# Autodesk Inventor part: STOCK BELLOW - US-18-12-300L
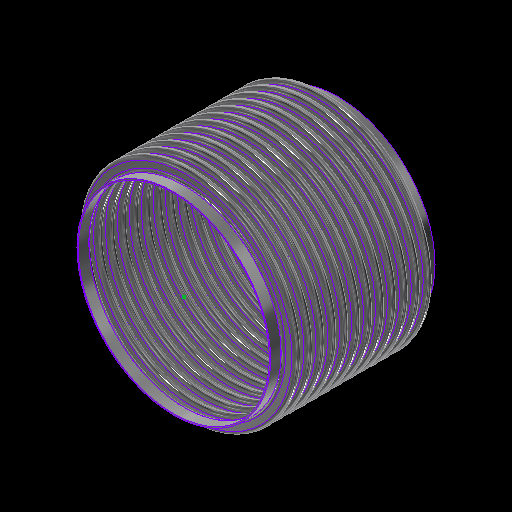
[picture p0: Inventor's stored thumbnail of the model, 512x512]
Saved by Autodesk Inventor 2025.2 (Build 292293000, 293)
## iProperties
Category: 16 GA (0.060 THICK)
RuleStatus: InUse
Created: 2024-01
Part Number: STOCK BELLOW - US-18-12-300L
Project: =STOCK BELLOWS: <Stock Number><SFILL>
Material: ASTM A240-304
Description: =STOCK BELLOWS: <Stock Number>, <SID_> I.D., <SOD_> O.D., <SPLY_> PLY, <Category>, <SNET_CONS> CONS.<PITCH_><STANGENT_> TANGENT<SFILL>
Document SubType Name: Sheet Metal
Designer: GS
Stock Number: U.S-18-12-300L
Surface Area: 28909 cm^2
Volume: 4365.44 cm^3
Sheet Metal Rule: Default
Appearance: STAINLESS STEEL
Mass: 35173.6 g
Density: 8.05729 g/cm^3
THK: 0.036
ID: 3.500
OD: 4.250
CONS_: 2
PITCH: 0.500
TANGENT: 0.500
BELLOWS_UPSET: 0.000
d79: 1.000
d82: 1.000
d83: 26.000
d84: 24.000
d174: 8
d214: 8
STHK_: 0.060
SID_: 18.000
SOD_: 20.500
SPITCH_: 1.125
STANGENT__: 1.000
SBELLOWS_UPSET_: 0.000
SDIFF_TAN: 1.000
d252: 2
d275: 2
d287: 0.050
d289: 0.500
d290: 0.000
SOD_NECK: 18 1/4
PLY: 1
PSET: 4.178
PBAR: 1.035
COUNTER: 1.500
NET_TUBE: 3.071
CONS: 2
S_CONS: 0
NET_CONS: 2
ID_M: 88.90 mm
OD_M: 107.95 mm
THK_M: 0.91 mm
ID_U: 3.500 in
OD_U: 4.250 in
THK_U: 0.036 in
TANGENT2: 0.500
TAN_TO_TAN: 1.000 in
d80: 2.571
d81: 10
SID: 2.375
SCONS_: 12
SPITCH: 0.250
STANGENT_: 1.000
SBELLOWS_UPSET: 0.000
SNET_CONS: 12
SS_CONS: 0
SCONS: 8
d190: 8
d191: 1
d192: 1
d193: 8
d194: 0
SIZE: 18.00
PRESSURE: 300
d230: 8
STANGENT: 4.000
SPLY_: 2
d233: 8
d234: 0
d263: 2
d265: 1
d268: 2
d269: 0
d286: 2
d288: 1
d291: 2
d292: 0
SREROLL: 0.750
BLETP: 1.000 ul
PRES_Copy: 85
MATTABLE: 20 GA (0.036 THICK)
PART_NUMBER: U.S-18-12-300L
PITCH_: =, <SPITCH_> PITCH,
CFILL: .
SFILL: .
MESH: ,
COMP: 2.29
EXT: 1.15
LAT: 0.53
ANG: 573
ASR: 7081
LSR: 21595
ANSR: 5724
PRES: 300
COMPM: 22.9
EXTM: 11.45
LATM: 5.30
ASRM: 1240.096
PRESM: 20.684
LSRM: 3781.932
ANSRM: 1002.444
TEMPMIN: 20
TEMPMAX: 800
TEMPMINM: -7
TEMPMAXM: 427
WEIGHTM: 35.174
WEIGHT: 77.544
Author: GS
Keywords: 20 GA (0.036 THICK)
Comments: =STOCK BELLOW - <STOCK NUMBER>
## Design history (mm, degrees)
sketch "Sketch2"
  geometry: L1 (0, -177.245)-(0, 562.856) reference; L2 (45.364, 0)-(44.45, 0); L3 (48.082, -2.718)-(50.343, -2.718); L4 (48.082, -3.632)-(50.343, -3.632); L5 (50.343, -9.982)-(48.082, -9.982); L6 (50.343, -9.068)-(48.082, -9.068); L7 (45.364, -12.7)-(44.45, -12.7); L8 (48.082, 0)-(48.082, -12.7); L9 (50.343, -6.35)-(53.975, -6.35); L10 (44.45, 0)-(44.45, -12.7); L11 (20.376, 102.841)-(20.376, 101.926); L12 (58.262, 457.127)-(58.262, 349.177); L13 (58.262, 444.427)-(58.262, 336.477); L14 (93.133, -58.817)-(93.133, -71.517); L15 (118.746, -66.401)-(118.746, -66.401); L16 (50.343, -9.068)-(50.343, -9.982); L17 (48.082, -9.068)-(48.082, -9.982); L18 (48.082, -9.525)-(50.343, -9.525); L19 (53.975, 0)-(53.975, -12.7); L20 (-50.343, -9.068)-(-50.343, -9.982); L21 (-50.343, -2.718)-(-48.082, -2.718); L22 (-50.343, -3.632)-(-48.082, -3.632); L23 (-48.082, -9.068)-(-50.343, -9.068); L24 (-50.343, -9.525)-(-48.082, -9.525); L25 (-48.082, -9.982)-(-50.343, -9.982); L26 (-48.082, -9.068)-(-48.082, -9.982); L27 (-44.45, 0.653)-(-44.45, -12.047); L28 (-48.082, -6.35)-(-44.45, -6.35); L29 (-50.343, 0.653)-(-50.343, -12.7); L30 (-53.061, 0)-(-53.975, 0); L31 (-53.975, 0)-(-53.975, -12.7); L32 (-53.061, -12.7)-(-53.975, -12.7); A1 r 2.718 centre (48.082, 0) between (45.364, 0) and (48.082, -2.718); A2 r 3.632 centre (48.082, 0) between (44.45, 0) and (48.082, -3.632); A3 r 3.632 centre (50.343, -6.35) between (50.343, -9.982) and (50.343, -2.718); A4 r 2.718 centre (50.343, -6.35) between (50.343, -9.068) and (50.343, -3.632); A5 r 2.718 centre (48.082, -12.7) between (48.082, -9.982) and (45.364, -12.7); A6 r 3.632 centre (48.082, -12.7) between (48.082, -9.068) and (44.45, -12.7); A7 r 3.175 centre (50.343, -6.35) between (50.343, -9.525) and (53.518, -6.35); A8 r 3.175 centre (48.082, -12.7) between (48.082, -9.525) and (44.907, -12.7); A9 r 2.718 centre (-50.343, -12.7) between (-50.343, -9.982) and (-53.061, -12.7); A10 r 2.718 centre (-48.082, -6.35) between (-48.082, -9.068) and (-48.082, -3.632); A11 r 3.175 centre (-48.082, -6.35) between (-48.082, -9.525) and (-44.907, -6.35); A12 r 3.632 centre (-48.082, -6.35) between (-48.082, -9.982) and (-48.082, -2.718); A13 r 3.175 centre (-50.343, -12.7) between (-50.343, -9.525) and (-53.518, -12.7); A14 r 3.632 centre (-50.343, -12.7) between (-50.343, -9.068) and (-53.975, -12.7); A15 r 2.718 centre (-50.343, 0) between (-53.061, 0) and (-50.343, -2.718); A16 r 3.632 centre (-50.343, 0) between (-53.975, 0) and (-50.343, -3.632); 10 further points
  constraints: 62 end point, 38 point on circle, 20 tangent, 16 centre point, 12 parallel, 9 midpoint, 7 vertical, 6 coincident, 6 concentric, 6 point on line, 4 equal radius, 4 perpendicular, 3 horizontal, 1 collinear, 1 horizontal alignment, 10 other
  dimensions: "THK" = 0.9144 distance of L11.start L11.end; "ID" = 88.9 distance of L11.end point (20.376, 13.026); "OD" = 107.95 distance of L12.start L12.end; "PITCH" = 12.7 distance of L12.start L13.start; "TANGENT" = 12.7 distance of L14.start L14.end; "BELLOWS_UPSET" = 0 distance of L15.start L15.end; "d43" = 88.9 diameter of L10 L1 (= ID); "d44" = 107.95 diameter of L9.end L1 (= OD); "d45" = 0.9144 distance between parallel lines of L5 L6 (computed from THK, PLY); "d46" = 3.6322 radius of A3 (computed from PITCH, THK, PLY); "UPSET_PITCH" = 12.7 distance of L2.end L7.end (derived); "SIDEWALL_ANGLE" = 360 deg dimension on L3 L9 (derived); "CON_GAP" = 5.4356 distance of point (48.082, -9.068) point (48.082, -3.632) (derived); "TAN1" = 4.98728 dimension on A8 (derived); "TAN2" = 4.98728 dimension on A7 (derived); "LEG1" = 2.2606 distance of L18.start L18.end (derived); "d278" = 0.9144 distance between parallel lines of L25 L23 (derived); "d279" = 3.6322 radius of A12 (derived); "d280" = 12.7 distance of L30.end L31.end (derived); "d281" = 360 deg dimension on L21 L28 (derived); "d282" = 5.4356 distance of point (-50.343, -9.068) point (-50.343, -3.632) (derived); "d283" = 4.98728 dimension on A13 (derived); "d284" = 4.98728 dimension on A11 (derived); "d285" = 2.2606 distance of L24.start L24.end (derived); "d293" = 88.9 diameter of L27 L1 (derived); "d294" = 107.95 diameter of L31 L1 (derived)
  node "Sketch Rectangular Pattern1" dims "d31" = 25.4, "ID" = 88.9
  node "Sketch Rectangular Pattern2" dims "d39" = 25.4, "PITCH" = 12.7
revolve "CONS" stored, may be unused: angle "d48" = 90 deg
node "BELLOW MIDPLANE"
pattern_linear "Rectangular Pattern2" dims "d52" = 12.7 (= UPSET_PITCH)
sketch "Sketch5"
  geometry: C1 r 45.364 at (0, 0) reference; C2 r 44.45 at (0, 0) reference
extrude "TANGENT" new body sketch "Sketch5" distance "d53" = 12.7 (= TANGENT); taper "d54" = 0 deg
revolve "SAMETAN" stored, may be unused: angle "d65" = 90 deg
revolve "DIFFTAN" stored, may be unused: angle "d70" = 90 deg
sketch "Sketch9"
  geometry: L1 (53.319, 0)-(-53.319, 0) reference; L2 (0, -17.78)-(0, 17.78) reference; L3 (38.085, 0)-(-38.085, 0); L4 (38.085, -11.906)-(38.085, 11.906); L5 (25.385, -11.906)-(25.385, 11.906); L6 (13.15, 11.906)-(13.15, -11.906); L7 (-25.385, -11.906)-(-25.385, 11.906); L8 (-38.085, -11.906)-(-38.085, 11.906); L9 (37.291, -11.906)-(37.291, 11.906); L10 (38.085, -11.906)-(37.291, -11.906); L11 (38.085, 11.906)-(37.291, 11.906); L12 (13.546, 11.906)-(12.753, 11.906); L13 (12.753, 11.906)-(12.753, -11.906); L14 (12.753, -11.906)-(13.546, -11.906); L15 (13.546, -11.906)-(13.546, 11.906); L16 (-13.546, 11.906)-(-13.546, -11.906); L17 (-13.15, 11.906)-(-13.15, -11.906); L18 (-13.546, -11.906)-(-12.753, -11.906); L19 (-12.753, -11.906)-(-12.753, 11.906); L20 (-12.753, 11.906)-(-13.546, 11.906); L21 (-38.085, -11.906)-(-37.291, -11.906); L22 (-37.291, -11.906)-(-37.291, 11.906); L23 (-37.291, 11.906)-(-38.085, 11.906); L24 (-38.085, 11.906)-(-38.085, -11.906); L25 (38.085, -0.397)-(-38.085, -0.397); L26 (-38.085, -0.397)-(-38.085, 0.397); L27 (-38.085, 0.397)-(38.085, 0.397); L28 (38.085, 0.397)-(38.085, -0.397); L29 (-38.085, 11.906)-(38.085, 11.906); L30 (38.085, 11.906)-(38.085, 12.7); L31 (38.085, 12.7)-(-38.085, 12.7); L32 (-38.085, 12.7)-(-38.085, 11.906); L33 (38.085, -11.906)-(-38.085, -11.906); L34 (-38.085, -11.906)-(-38.085, -12.7); L35 (-38.085, -12.7)-(38.085, -12.7); L36 (38.085, -12.7)-(38.085, -11.906); 30 further points
  constraints: 68 end point, 13 midpoint, 13 parallel, 8 horizontal, 7 perpendicular, 6 equal length, 3 point on line, 2 vertical, 14 other
  dimensions: "d115" = 23.8125 distance of L4.start L4.end (derived); "d116" = 12.7 distance between parallel lines of L4 L5 (derived); "d117" = 12.23516 distance between parallel lines of L5 L6 (derived); "d125" = 38.53427 distance between parallel lines of L7 L6 (derived); "d127" = 12.7 distance between parallel lines of L8 L7 (derived); "d128" = 24.93516 distance between parallel lines of L6 L4 (derived); "d130" = 76.16943 distance between parallel lines of L8 L4 (derived); "RULER_THK" = 0.79375 distance between parallel lines of L4 L9; "d135" = 0.79375 distance of L13.end L14.end (derived); "d138" = 26.29911 distance of L13.end L16.end (derived); "d143" = 0.79375 distance of L22.end L8.end (derived); "d144" = 0.79375 distance between parallel lines of L27 L25 (derived)
extrude "RULER" join sketch "Sketch9" distance "d149" = 0.79375 (derived); taper "d150" = 0 deg
extrude "BARS" join sketch "Sketch9" distance "d151" = 0.79375 (derived); taper "d152" = 0 deg
pattern_linear "Rectangular Pattern4" dims "d155" = 26.29911 (derived)
sketch "Sketch13"
  geometry: L1 (93.149, -52.467)-(93.149, -77.867); L2 (231.648, 0)-(228.6, 0); L3 (231.648, -28.575)-(228.6, -28.575); L4 (251.682, -22.955)-(237.268, -22.955); L5 (251.682, -19.907)-(237.268, -19.907); L6 (251.682, -14.287)-(260.35, -14.287); L7 (237.268, -5.62)-(251.682, -5.62); L8 (237.268, 0)-(237.268, -28.575); L9 (228.6, 0)-(228.6, -28.575); L10 (58.254, 24.269)-(58.254, -496.431); L11 (58.254, -4.306)-(58.254, -525.006); L12 (58.254, -61.456)-(58.254, -582.156); L13 (58.254, -90.031)-(58.254, -610.731); L14 (58.254, -118.606)-(58.254, -639.306); L15 (58.254, -147.181)-(58.254, -667.881); L16 (58.254, -175.756)-(58.254, -696.456); L17 (58.254, -32.881)-(58.254, -553.581); L18 (20.376, 103.45)-(20.376, 101.926); L19 (237.268, -8.668)-(251.682, -8.668); L20 (0, -856.437)-(0, 263.431) reference; L21 (-52.07, 0)-(312.42, 0) reference; A1 r 5.62 centre (237.268, 0) between (231.648, 0) and (237.268, -5.62); A2 r 5.62 centre (237.268, -28.575) between (237.268, -22.955) and (231.648, -28.575); A3 r 8.668 centre (237.268, -28.575) between (237.268, -19.907) and (228.6, -28.575); A4 r 5.62 centre (251.682, -14.287) between (251.682, -19.907) and (251.682, -8.668); A5 r 8.668 centre (251.682, -14.287) between (251.682, -22.955) and (251.682, -5.62); A6 r 8.668 centre (237.268, 0) between (228.6, 0) and (237.268, -8.668); 6 further points; 1 other entity
  constraints: 38 end point, 15 point on circle, 9 tangent, 6 centre point, 6 parallel, 5 vertical alignment, 4 point on line, 4 vertical, 3 coincident, 3 concentric, 2 collinear, 2 equal radius, 1 horizontal, 1 perpendicular, 23 other
  dimensions: "SBELLOWS_UPSET_" = 0 distance of point (118.762, -66.401) point (118.762, -66.401); "STOTAL_THK_BELLOW__" = 3.048 distance between parallel lines of L4 L5 (derived); "d224" = 8.66775 radius of A5 (derived); "d225" = 28.575 distance of L2.end L3.end (derived); "SSIDEWALL_ANGLE_" = 360 deg dimension on L7 L6 (derived); "SSCON_GAP_" = 11.2395 distance of point (237.268, -19.907) point (237.268, -8.668) (derived); "d235" = 457.2 diameter of L9 L20 (derived); "d236" = 520.7 diameter of L6.end L20 (derived)
  node "Sketch Rectangular Pattern4" dims "d228" = 25.4
  node "Sketch Rectangular Pattern5" dims "d229" = 25.4
revolve "SBELLOW" stored, may be unused: angle "d197" = 90 deg
pattern_linear "Rectangular Pattern5" dims "d204" = 28.575 (derived)
revolve "STANGENT" stored, may be unused: angle "d240" = 90 deg
revolve "SSAMETAN" stored, may be unused: angle "d241" = 90 deg
revolve "SDIFFTAN" stored, may be unused: angle "d246" = 90 deg
revolve "INVCON" stored, may be unused: angle "d295" = 90 deg
pattern_linear "Rectangular Pattern6" dims "d298" = 12.7 (derived)
revolve "INVTANGENT" stored, may be unused: angle "d302" = 90 deg
revolve "INVSAMETAN" stored, may be unused: angle "d307" = 90 deg
revolve "INVDIFFTAN" stored, may be unused: angle "d312" = 90 deg
sketch "ID BELLOW MOUNT CALC"
  geometry: L1 (44.45, 0)-(38.1, 0); L2 (38.1, 0)-(38.1, 12.7); L3 (38.1, 12.7)-(44.45, 12.7); L4 (44.45, 12.7)-(44.45, 0); L5 (36.513, 12.7)-(35.598, 12.7); L6 (35.598, 12.7)-(35.598, 0); L7 (35.598, 0)-(36.513, 0); L8 (36.513, 0)-(36.513, 12.7); L9 (0, -2.54)-(0, 15.24) reference; L10 (-8.89, 0)-(53.34, 0) reference; 1 further point
  constraints: 16 end point, 5 parallel, 2 collinear, 2 horizontal, 2 perpendicular
  dimensions: "d314" = 12.7 distance of L5.end L6.end (derived); "d315" = 0.9144 distance of L5.start L5.end (derived); "IG" = 1.5875 distance between parallel lines of L2 L8; "PIPE_OD" = 88.9 diameter of L4 L9; "PIPE_WALL" = 6.35 distance of L2.end L3.end; "ID_MT_BELLOW" = 71.1962 diameter of L6 L9 (derived)
revolve "CFILL" stored, may be unused: angle "d320" = 90 deg
pattern_linear "Rectangular Pattern7" dims "d323" = 12.7 (derived)
revolve "SFILL" stored, may be unused: angle "d324" = 90 deg
pattern_linear "Rectangular Pattern8" dims "d327" = 28.575 (derived)
node "STOCK BELLOW MIDPLANE"
node "BELLOW"
sketch "Sketch6"
  geometry: L1 (-12.7, 45.364)-(0, 45.364); L2 (0, 45.364)-(0, 44.45); L3 (0, 44.45)-(-12.7, 44.45); L4 (-12.7, 44.45)-(-12.7, 45.364); L5 (10.16, 0)-(-60.96, 0) reference; L6 (-38.1, -89.422)-(-38.1, 153.44) reference; 1 further point
  constraints: 8 end point, 2 parallel, 1 horizontal, 1 perpendicular
  dimensions: "d61" = 12.7 distance of L2.end L3.end (derived); "d62" = 0.9144 distance of L1.end L2.end (derived); "d63" = 88.9 diameter of L3 L5 (derived); "d64" = 25.4 distance between parallel lines of L4 L6 (derived)
sketch "Sketch12"
  geometry: 1 further point
sketch "Sketch14"
  geometry: L1 (-25.4, 231.648)-(0, 231.648); L2 (0, 231.648)-(0, 228.6); L3 (0, 228.6)-(-25.4, 228.6); L4 (-25.4, 228.6)-(-25.4, 231.648); L5 (5.08, 0)-(-30.48, 0) reference; L6 (0, -46.33)-(0, 277.978) reference; 1 further point
  constraints: 8 end point, 2 parallel, 1 collinear, 1 horizontal, 1 perpendicular
  dimensions: "d237" = 3.048 distance of L3.end L1.start (derived); "d238" = 457.2 diameter of L3 L5 (derived); "d239" = 25.4 distance of L1.start L1.end (derived); "SOD_NECK" = 463.296 diameter of L1 L5 (derived)
sketch "Sketch15"
  geometry: L1 (-46.33, 0)-(277.978, 0) reference; L2 (228.6, -342.9)-(231.648, -342.9); L3 (231.648, -342.9)-(231.648, -368.3); L4 (231.648, -368.3)-(228.6, -368.3); L5 (228.6, -368.3)-(228.6, -342.9); L6 (0, -444.5)-(0, 88.9) reference; 1 further point
  constraints: 8 end point, 2 parallel, 1 horizontal, 1 perpendicular
  dimensions: "d205" = 25.4 distance of L4.end L2.start (derived); "d206" = 3.048 distance of L3.end L4.end (derived); "d207" = 457.2 diameter of L5 L6 (derived); "d208" = 342.9 distance between parallel lines of L1 L2 (derived)
node "TANGENT_"
node "SAME_TAN"
sketch "Sketch8"
  geometry: L1 (45.364, -25.4)-(44.45, -25.4); L2 (44.45, -25.4)-(44.45, -38.1); L3 (44.45, -38.1)-(45.364, -38.1); L4 (45.364, -38.1)-(45.364, -25.4); L5 (0, -48.26)-(0, 22.86) reference; L6 (-89.422, 0)-(153.44, 0) reference; 1 further point
  constraints: 8 end point, 2 parallel, 1 horizontal, 1 perpendicular
  dimensions: "d66" = 88.9 diameter of L2 L5 (derived); "TOTAL_THK_BELLOW" = 0.9144 distance of L2.end L3.end (derived); "d68" = 25.4 distance between parallel lines of L1 L6 (derived); "d69" = 12.7 distance of L1.end L2.end (derived)
node "DIFF_TAN"
node "Sketch Rectangular Pattern3" dims "d138" = 26.29911 (derived), "d141" = 25.4
node "SBELLOW_"
node "STANGENT_"
node "SSAME_TAN"
sketch "Sketch16"
  geometry: L1 (231.648, -342.9)-(228.6, -342.9); L2 (228.6, -342.9)-(228.6, -368.3); L3 (228.6, -368.3)-(231.648, -368.3); L4 (231.648, -368.3)-(231.648, -342.9); L5 (0, -444.5)-(0, 88.9) reference; L6 (-46.33, 0)-(277.978, 0) reference; 1 further point
  constraints: 8 end point, 2 parallel, 1 horizontal, 1 perpendicular
  dimensions: "SDIFF_TAN" = 25.4 distance of L3.end L1.start; "d243" = 3.048 distance of L2.end L3.end (derived); "d244" = 342.9 distance between parallel lines of L1 L6 (derived); "d245" = 457.2 diameter of L2 L5 (derived)
node "SDIFF_TAN"
body "Solid15"
sketch "Sketch17"
  geometry: L1 (53.975, 12.7)-(53.061, 12.7); L2 (53.061, 12.7)-(53.061, 0); L3 (53.061, 0)-(53.975, 0); L4 (53.975, 0)-(53.975, 12.7); L5 (0, -2.54)-(0, 15.24) reference; L6 (-10.795, 0)-(64.77, 0) reference; 2 further points
  constraints: 8 end point, 2 parallel, 1 horizontal, 1 midpoint, 1 perpendicular, 1 point on line
  dimensions: "INVTANGENT" = 12.7 distance of L3.end L1.start (derived); "d300" = 0.9144 distance of L1.start L1.end (derived); "d301" = 107.95 diameter of L4 L5 (derived)
body "Solid16"
sketch "Sketch18"
  geometry: L1 (53.975, -25.4)-(53.061, -25.4); L2 (53.061, -25.4)-(53.061, -38.1); L3 (53.061, -38.1)-(53.975, -38.1); L4 (53.975, -38.1)-(53.975, -25.4); L5 (-10.795, 0)-(64.77, 0) reference; L6 (0, -48.26)-(0, 22.86) reference; 1 further point
  constraints: 8 end point, 2 parallel, 1 horizontal, 1 perpendicular
  dimensions: "d303" = 25.4 distance between parallel lines of L1 L5 (derived); "d304" = 12.7 distance of L3.end L1.start (derived); "d305" = 0.9144 distance of L2.end L3.end (derived); "d306" = 107.95 diameter of L4 L6 (derived)
body "Solid17"
sketch "Sketch19"
  geometry: L1 (53.975, -25.4)-(53.061, -25.4); L2 (53.061, -25.4)-(53.061, -38.1); L3 (53.061, -38.1)-(53.975, -38.1); L4 (53.975, -38.1)-(53.975, -25.4); L5 (0, -48.26)-(0, 22.86) reference; L6 (-10.795, 0)-(64.77, 0) reference; 1 further point
  constraints: 8 end point, 2 parallel, 1 horizontal, 1 perpendicular
  dimensions: "d308" = 12.7 distance of L1.end L2.end (derived); "d309" = 107.95 diameter of L4 L5 (derived); "d310" = 0.9144 distance of L2.end L3.end (derived); "d311" = 25.4 distance between parallel lines of L1 L6 (derived)
body "Solid18"
body "Solid19"
body "Solid20"
other parameters: "BMPL" = -171.45, "PSET" = 106.1212 (computed from OD, THK, PLY) [user parameter], "PBAR" = 26.29911 (= 0.570796 x PITCH + OD - ID) [user parameter; used in 1 equation term], "COUNTER" = 15 [user parameter], "NET_TUBE" = 77.99823 (computed from CONS_, PBAR, TANGENT) [user parameter], "S_CONS" = 0 [user parameter; used in 1 equation term], "ID_M" = 88.9 (= ID) [user parameter], "OD_M" = 107.95 (= OD) [user parameter], "THK_M" = 0.9144 (= THK) [user parameter], "ID_U" = 88.9 (= ID) [user parameter], "OD_U" = 107.95 (= OD) [user parameter], "THK_U" = 0.9144 (= THK) [user parameter], "D_UNITS" = 0 [user parameter], "TANGENT2" = 12.7 [user parameter], "TAN_TO_TAN" = 25.4 [user parameter], "OD_NECK" = 90.7288 [user parameter], "d79" = 25.4, "d80" = 65.29823 [user parameter], "d82" = 25.4, "d83" = 660.4, "d84" = 609.6, "sa_0" = 4, "FRAME_THK" = 0.79375 [user parameter], "CON_FLAT" = 12.23516 [user parameter], "SID" = 60.325 [user parameter], "SPITCH" = 6.35 [user parameter], "STANGENT_" = 25.4 [user parameter], "SBELLOWS_UPSET" = 0 [user parameter], "SS_CONS" = 0 [user parameter], "STAN_TO_TAN_" = 342.9 [user parameter], "d100" = 3.048 [user parameter], "d191" = 25.4 [user parameter], "d194" = 0 [user parameter], "STANGENT" = 101.6 [user parameter], "d234" = 0 [user parameter], "SUPSET_PITCH_" = 28.575 [user parameter], "d269" = 0 [user parameter], "d287" = 1.27, "d289" = 12.7, "d290" = 0, "d292" = 0 [user parameter], "Thickness" = 3.048 (derived), "KFactor" = 4.4, "BendRadius" = 3.048 (derived), "BendReliefWidth" = 3.048 (derived), "BendReliefDepth" = 1.524 (derived), "CornerReliefSize" = 12.192 (derived), "SeamGap" = 0.00508, "MinimumRemnant" = 6.096 (derived), "TransitionRadius" = 3.048 (derived), "JacobiRadiusSize" = 3.048 (derived), "GapSize" = 3.048 (derived), "SREROLL" = 19.05 [user parameter], "CUR_STK_PITCH" = 28.575 [user parameter], "d328" = -171.45 (derived), "ASR" = 70810 [user parameter], "LSR" = 215950 [user parameter], "ANSR" = 57240 [user parameter], "BLETP" = 1 [user parameter], "ASRM" = 12400.9553 [user parameter], "PRESM" = 206.83949 [user parameter], "LSRM" = 37819.3235 [user parameter], "ANSRM" = 10024.4412 [user parameter], "TEMPMIN" = 2664.83333 [user parameter], "TEMPMAX" = 6998.16667 [user parameter], "TEMPMINM" = 2664.83333 [user parameter], "TEMPMAXM" = 6998.16667 [user parameter], "WEIGHT" = 351.73588 [user parameter], "WEIGHTM" = 0.35174 [user parameter]
